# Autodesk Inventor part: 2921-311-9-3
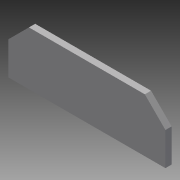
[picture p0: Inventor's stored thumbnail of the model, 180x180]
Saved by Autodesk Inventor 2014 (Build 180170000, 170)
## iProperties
Company: NHTSA/VRTC
Created: 2012-02
Part Number: 2921-311-9-3
Project: CHILD SIDE IMPACT SLED
Material: Steel
Description: SHT. #16 Ga. x 13 (0.51") x 38.1 (1.5")
Document SubType Name: Modeling
Designer: Dave Walker
Mass: 5.60763 g
Surface Area: 10.8694 cm^2
Volume: 0.714348 cm^3
Density: 7.85 g/cm^3
Appearance: Steel
Title: BENCH FRAME TUBE #8 CAP #2
Subject: Cild Side Impact Sled
Author: Dave Walker
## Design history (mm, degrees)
sketch "Sketch1"
  geometry: L1 (-14.05, 6.5)-(14.05, 6.5); L2 (19.05, 1.5)-(19.05, -6.5); L3 (19.05, -6.5)-(-19.05, -6.5); L4 (-19.05, -6.5)-(-19.05, 1.5); L5 (0, 9.1)-(0, -9.1) reference; L6 (-26.67, 0)-(26.67, 0) reference; L7 (-14.05, 6.5)-(-19.05, 1.5); L8 (14.05, 6.5)-(19.05, 1.5); 2 further points
  constraints: 12 end point, 4 point on line, 2 parallel, 1 horizontal, 1 perpendicular, 2 other
  dimensions: "d0" = 13 distance of L3.end point (-19.05, 6.5); "d1" = 38.1 distance of L2.end L3.end; "d2" = 5 distance of L1.start point (-19.05, 6.5); "d3" = 5 distance of L4.end point (-19.05, 6.5) (= d2); "d4" = 5 distance of L1.end point (19.05, 6.5) (= d2); "d5" = 5 distance of L2.start point (19.05, 6.5) (= d4)
extrude "Extrusion1" new body sketch "Sketch1" distance "d6" = 1.51892; taper "d7" = 0 deg
body "Solid1"
